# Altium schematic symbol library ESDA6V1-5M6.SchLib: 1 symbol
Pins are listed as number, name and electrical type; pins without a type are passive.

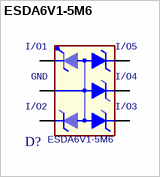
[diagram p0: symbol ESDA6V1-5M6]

## ESDA6V1-5M6
designator D?
footprint ST_QFN50P100X145X60-6L
pins: 1 I/O1, 2 GND, 3 I/O2, 4 I/O3, 5 I/O4, 6 I/O5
